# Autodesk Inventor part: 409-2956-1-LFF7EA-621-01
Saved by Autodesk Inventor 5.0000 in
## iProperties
Created: 2010-06
Part Number: 409-2956-1-LFF7EA-621-01
Cost Center: 0 lbmass
Material: A36 STEEL PLATE
Document SubType Name: Sheet Metal
Designer: S. Boerckel
Authority: 0 in^3
Mass: 6361.08 g
Surface Area: 856.126 cm^2
Volume: 809.298 cm^3
Density: 7.86 g/cm^3
Flat Pattern Width: 12.7 cm
Flat Pattern Length: 25.4 cm
Flat Pattern Area: 322.58 cm^2
Sheet Metal Rule: 1" HR PLATE
Sheet Metal Width: 10.0000 in
Sheet Metal Length: 50.0000 in^2
Description: STAINER FOOT PLATE
User Status: BURN
SaveDate: 2008-01-15
SaveTime: 10:24
FileName: Sheet Metal
Wide: =<Flat Pattern Width>cm
Length: =<Flat Pattern Length>cm
Thickness: 1.0000 in
SMR: =<Sheet Metal Rule> - <Material>
Author: S. Boerckel
Revision Number: 0
Subject: DEMIN WATER FORWARDING PUMP SKID-7EA
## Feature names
1. Hole1
2. Plate1
